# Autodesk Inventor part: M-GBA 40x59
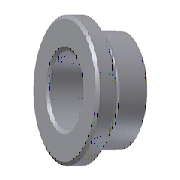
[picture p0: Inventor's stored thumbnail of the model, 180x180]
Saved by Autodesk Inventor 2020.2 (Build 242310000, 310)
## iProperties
Manager: www.cadconsulting.pl
Company: Fabian Stasiak CAD Consulting
Created: 2014-02
Part Number: M-GBA 40x59
Material: SUJ 2
Description: GUIDE BUSH
Document SubType Name: Modeling
Designer: F.Stasiak
Standard Revision: 1
Manufacturer: FUTABA
Language: pl-PL
Size Designation: 40x59
Categories: <MemberInstance><Categories><Category DisplayName="Forma wtryskowa" InternalName="349578f2-f4d4-4954-8c09-8e99297a61c0" Mnemonic="MOLD"><Category DisplayName="K
Density: 7.85 g/cm^3
Appearance: Domyślna
Catalog Web Link: www.expertbooks.pl
IsCustomPart: 0
Author: F.Stasiak
Subject: Zbiór ćwiczeń. Autodesk Inventor 2020. Kurs Professional
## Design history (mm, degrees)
sketch "Sketch1"
  geometry: L1 (0, -16.2)-(0, 6.2) reference; L2 (0, 10)-(30.5, 10); L3 (30.5, 10)-(30.5, 0); L4 (30.5, 0)-(27, 0); L5 (27, 0)-(27, -2); L6 (27, -2)-(27.5, -2); L7 (27.5, -2)-(27.5, -46); L8 (27.5, -46)-(27.25, -46); L9 (27.25, -46)-(27.25, -49); L10 (27.25, -49)-(0, -49); 1 further point
  constraints: 18 end point, 4 perpendicular, 2 parallel, 2 point on line, 1 horizontal alignment
  dimensions: "d0" = 59 distance between parallel lines of L10 L2 (= B); "d2" = 10 distance between parallel lines of L4 L2 (= T1); "d3" = 55 diameter of L7 L1 (= D); "d4" = 3 distance between parallel lines of L10 L8; "d5" = 54.5 diameter of L9 L1 (= D_Guide); "d6" = 61 diameter of L3 L1 (= D2); "d7" = 0.5 distance between parallel lines of L7 L5; "d8" = 2 distance between parallel lines of L4 L6
revolve "Revolution1" sketch "Sketch1" stored, may be unused: angle "d13" = 90 deg
sketch "Sketch2"
  geometry: L1 (-27.25, -49)-(27.25, -49) reference; L2 (0, -20.2)-(0, 30.2) reference; L3 (20, 10)-(20, -49); L4 (20, 10)-(20.25, 10); L5 (20.25, 10)-(20.25, 69); L6 (20.25, 69)-(0, 69); L7 (20, -49)-(0, -49); L8 (0, 69)-(0, -49)
  constraints: 12 end point, 3 perpendicular, 3 point on line, 1 collinear, 1 midpoint, 1 parallel
  dimensions: "d18" = 40 diameter of L3 L2 (= d_); "d20" = 59 distance between parallel lines of L1 L4 (= L1); "d21" = 59 distance between parallel lines of L4 L6 (= B); "d22" = 40.5 diameter of L5 L2 (= d1)
revolve "Revolution2" sketch "Sketch2" stored, may be unused: angle "d23" = 90 deg
chamfer "Chamfer1" distance "d24" = 0.5; stored, may be unused: second distance "d25" = 2, angle "d26" = 45 deg
fillet "Fillet1" dims "d27" = 0.3
fillet "Fillet2" dims "d28" = 0.8
body "Solid1"
other parameters: "d_" = 40 [user parameter; used in 1 equation term], "d1" = 40.5 [user parameter; used in 1 equation term], "L1" = 59 [user parameter; used in 1 equation term], "D" = 55 [user parameter; used in 1 equation term], "D2" = 61 [user parameter; used in 1 equation term], "B" = 59 [user parameter; used in 2 equation terms], "T1" = 10 [user parameter; used in 1 equation term], "D_Guide" = 54.5 [user parameter; used in 1 equation term], "d29" = 0, "d30" = 0, "d31" = 0
